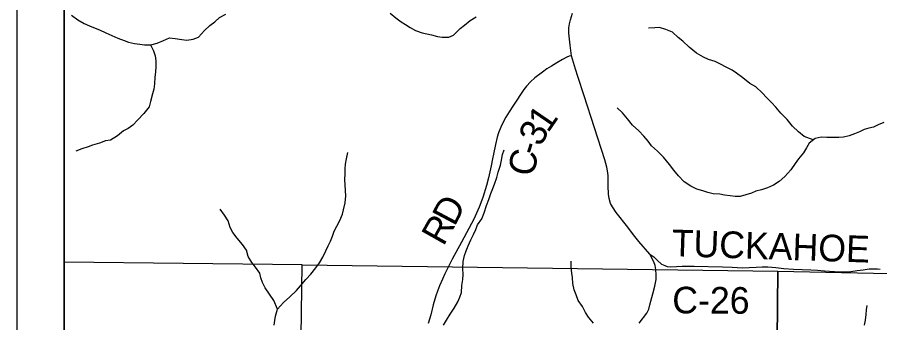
# Model space of a CAD drawing. Extents: x 0 to 34, y 0 to 22.
# Drawn here: x 23.417 to 25.254, y 19.532 to 20.183 of the extents above; entities that cross this region are included whole.
import ezdxf

# ---------------------------------------------------------------- set-up
doc = ezdxf.new("R2010")
doc.units = 0
for name, color, linetype in [('GM_X_Corporation', 7, 'Continuous'), ('GM_X_County_Road', 7, 'Continuous'), ('GM_X_County_Road_Text', 7, 'Continuous'), ('GM_X_Minor_River', 7, 'Continuous'), ('GM_X_State_Route', 7, 'Continuous'), ('SH_Data', 7, 'Continuous')]:
    doc.layers.add(name, color=color, linetype=linetype)

msp = doc.modelspace()

# ---------------------------------------------------------------- linework, layer by layer
at = {"layer": 'GM_X_Corporation'}
msp.add_lwpolyline([(27.0234, 16.6611), (27.0349, 17.5522), (27.0419, 17.8236), (27.0487, 18.5805), (27.0719, 19.3912), (27.0733, 19.498), (27.0761, 19.6806), (27.0864, 20.0138), (27.0885, 20.1139), (27.0907, 20.123), (27.0873, 20.2665), (27.0031, 20.2673), (26.7822, 20.2704), (26.7196, 20.2707), (26.6351, 20.2734), (26.5702, 20.276), (26.2533, 20.2773), (25.4507, 20.2949), (24.5249, 20.3107), (24.0688, 20.3165), (24.0328, 20.3169), (23.5167, 20.3276), (23.5167, 14.5642)], dxfattribs=at)
msp.add_lwpolyline([(27.0234, 16.6611), (27.0349, 17.5522), (27.0419, 17.8236), (27.0487, 18.5805), (27.0719, 19.3912), (27.0733, 19.498), (27.0761, 19.6806), (27.0864, 20.0138), (27.0885, 20.1139), (27.0907, 20.123), (27.0873, 20.2665), (27.0031, 20.2673), (26.7822, 20.2704), (26.7196, 20.2707), (26.6351, 20.2734), (26.5702, 20.276), (26.2533, 20.2773), (25.4507, 20.2949), (24.5249, 20.3107), (24.0688, 20.3165), (24.0328, 20.3169), (23.5167, 20.3276), (23.5167, 14.5642)], dxfattribs=at)
for points in [[(23.5167, 19.661), (23.5167, 18.6437), (24.0091, 18.6407), (24.0234, 19.6557)], [(24.0234, 19.6557), (25.037, 19.6422), (25.0268, 18.6245), (24.0091, 18.6407)], [(25.037, 19.6422), (26.0559, 19.6207), (26.0385, 18.6067), (25.0268, 18.6245)]]:
    msp.add_lwpolyline(points, close=True, dxfattribs=at)
at = {"layer": 'GM_X_County_Road'}
for points in [[(24.5973, 20.1011), (24.592, 20.1001), (24.5871, 20.0979), (24.5783, 20.093), (24.5663, 20.0861), (24.5546, 20.0791), (24.5448, 20.073), (24.5358, 20.0665), (24.519, 20.0542), (24.5099, 20.0458), (24.5013, 20.0361), (24.4956, 20.0291), (24.474, 19.996), (24.4644, 19.9818), (24.4573, 19.9703), (24.4516, 19.9598), (24.4466, 19.9489), (24.4421, 19.937), (24.4393, 19.9279), (24.4352, 19.912), (24.4312, 19.8916), (24.4293, 19.8817), (24.4262, 19.8665), (24.4203, 19.8412), (24.4163, 19.8248), (24.4086, 19.7989), (24.4007, 19.7785), (24.3896, 19.7527), (24.3632, 19.704), (24.3429, 19.6678), (24.3273, 19.6364), (24.3222, 19.6248), (24.3161, 19.6112), (24.3117, 19.5997), (24.3084, 19.5899), (24.3028, 19.5706), (24.2974, 19.549), (24.2923, 19.5303)], [(24.7643, 19.6782), (24.7726, 19.6728), (24.7804, 19.6649), (24.7889, 19.6569), (24.7959, 19.654), (24.8012, 19.6521), (24.8079, 19.6512), (24.8208, 19.6524), (24.8331, 19.653), (24.8583, 19.6529), (24.9193, 19.6513), (24.9395, 19.6508), (24.9607, 19.6494), (24.9906, 19.6507), (25.0035, 19.6514), (25.0158, 19.6513), (25.0329, 19.6499), (25.0497, 19.6477), (25.07, 19.6464), (25.0887, 19.6458), (25.1068, 19.645), (25.1211, 19.6441), (25.1362, 19.6432), (25.1573, 19.6411), (25.1669, 19.6405), (25.1783, 19.6404), (25.192, 19.6417), (25.2059, 19.6433), (25.2188, 19.6452), (25.2314, 19.6468), (25.2411, 19.6474), (25.2494, 19.6471), (25.2548, 19.6464)]]:
    msp.add_lwpolyline(points, dxfattribs=at)
at = {"layer": 'GM_X_Minor_River'}
for points in [[(24.2114, 20.1917), (24.2232, 20.1823), (24.2342, 20.1732), (24.2437, 20.1679), (24.254, 20.1615), (24.265, 20.1547), (24.2791, 20.1498), (24.2889, 20.1479), (24.2988, 20.1457), (24.3121, 20.1423), (24.3216, 20.1405), (24.336, 20.1409), (24.3459, 20.1451), (24.3599, 20.1592), (24.3693, 20.1664), (24.3818, 20.176), (24.3943, 20.1844)], [(23.5322, 20.1878), (23.5455, 20.1776), (23.5592, 20.1701), (23.5706, 20.1652), (23.5824, 20.1599), (23.5919, 20.1562), (23.6052, 20.1497), (23.6185, 20.1441), (23.6306, 20.1384), (23.6443, 20.1335), (23.6538, 20.1305), (23.6663, 20.1275), (23.6781, 20.1257), (23.688, 20.1242), (23.7009, 20.1242), (23.7149, 20.1281), (23.7282, 20.1338), (23.741, 20.1392), (23.7528, 20.1381), (23.7672, 20.1355), (23.7782, 20.1344), (23.7915, 20.1367), (23.8029, 20.1406), (23.8154, 20.155), (23.8271, 20.1657), (23.8373, 20.1737), (23.8472, 20.1825), (23.8612, 20.1901)], [(25.1122, 19.9218), (25.0931, 19.9292), (25.0806, 19.939), (25.068, 19.9515), (25.057, 19.9651), (25.0433, 19.9788), (25.0323, 19.9917), (25.0231, 20.0019), (25.0136, 20.0117), (25.0037, 20.022), (24.9897, 20.0348), (24.9771, 20.0424), (24.9623, 20.0545), (24.949, 20.0643), (24.9395, 20.0707), (24.927, 20.0768), (24.9148, 20.0832), (24.903, 20.0889), (24.8893, 20.093), (24.8787, 20.0979), (24.8639, 20.107), (24.8479, 20.1198), (24.8342, 20.1323), (24.8247, 20.1403), (24.8126, 20.1516), (24.7985, 20.1573), (24.7848, 20.1614), (24.7746, 20.1606), (24.7613, 20.1598)], [(23.7005, 20.1242), (23.7066, 20.1114), (23.7104, 20.1007), (23.7116, 20.0905), (23.7116, 20.0783), (23.7109, 20.0665), (23.7098, 20.0555), (23.709, 20.0415), (23.7079, 20.0297), (23.7049, 20.0198), (23.7008, 20.0038), (23.6974, 19.992), (23.686, 19.9783), (23.6732, 19.9646), (23.6626, 19.9532), (23.6531, 19.9459), (23.6429, 19.941), (23.6304, 19.9307), (23.6152, 19.9215), (23.605, 19.9196), (23.5917, 19.9149), (23.5773, 19.9107), (23.5674, 19.9073), (23.5542, 19.9027), (23.5413, 19.8981)], [(25.2623, 19.959), (25.2509, 19.954), (25.2407, 19.9487), (25.2308, 19.9471), (25.2206, 19.944), (25.2107, 19.9391), (25.2001, 19.9348), (25.1891, 19.9303), (25.1766, 19.9276), (25.1671, 19.9271), (25.1542, 19.9271), (25.141, 19.9267), (25.1288, 19.9274), (25.1163, 19.9251), (25.1038, 19.9152), (25.0977, 19.9053), (25.0913, 19.8946), (25.0811, 19.8813), (25.0739, 19.8717), (25.0645, 19.858), (25.0516, 19.8436), (25.0399, 19.8333), (25.0274, 19.8256), (25.0145, 19.8195), (25.0024, 19.8157), (24.9902, 19.8126), (24.9807, 19.8084), (24.969, 19.8045), (24.9569, 19.8011), (24.9462, 19.801), (24.9356, 19.8029), (24.9231, 19.8044), (24.9136, 19.8059), (24.8992, 19.8073), (24.8874, 19.8096), (24.8768, 19.8137), (24.8642, 19.8167), (24.8517, 19.8231), (24.8373, 19.8322), (24.8255, 19.8455), (24.8152, 19.8572), (24.806, 19.8693), (24.7931, 19.8852), (24.7802, 19.8977), (24.768, 19.9095), (24.7608, 19.9193), (24.7516, 19.9296), (24.741, 19.9409), (24.7273, 19.953), (24.7166, 19.9671), (24.706, 19.9799), (24.6946, 19.9902)], [(24.3887, 19.7205), (24.3936, 19.7312), (24.3973, 19.7407), (24.406, 19.7536), (24.4113, 19.7662), (24.4166, 19.7818), (24.4215, 19.7951), (24.4256, 19.808), (24.4294, 19.8183), (24.4332, 19.8278), (24.4384, 19.8419), (24.4414, 19.8529), (24.446, 19.8681), (24.4482, 19.8784), (24.4505, 19.8909), (24.4538, 19.9004)], [(23.9638, 19.5268), (23.9653, 19.5367), (23.9668, 19.5462), (23.9713, 19.5614), (23.9838, 19.5751), (23.9974, 19.5873), (24.0114, 19.6011), (24.0197, 19.6106), (24.0315, 19.6243), (24.0421, 19.6357), (24.0526, 19.6495), (24.0606, 19.6601), (24.0674, 19.6719), (24.0738, 19.6852), (24.0791, 19.6959), (24.084, 19.7062), (24.0881, 19.7164), (24.0915, 19.7275), (24.0972, 19.7381), (24.1036, 19.7503), (24.1093, 19.7633), (24.1119, 19.7728), (24.1153, 19.788), (24.1164, 19.8024), (24.116, 19.8134), (24.1152, 19.8267), (24.1148, 19.8362), (24.1151, 19.851), (24.1155, 19.8605), (24.1162, 19.8704), (24.1177, 19.8818), (24.1207, 19.8951)], [(23.9711, 19.5609), (23.9633, 19.58), (23.9538, 19.5929), (23.9446, 19.6069), (23.9393, 19.6183), (23.9358, 19.6282), (23.9331, 19.638), (23.924, 19.6505), (23.9164, 19.6604), (23.9088, 19.6733), (23.9053, 19.6866), (23.8966, 19.6987), (23.8848, 19.7127), (23.8756, 19.7248), (23.8703, 19.7355), (23.8657, 19.7495), (23.8581, 19.7616), (23.8486, 19.7745)], [(24.3243, 19.5273), (24.3307, 19.5379), (24.3386, 19.5505), (24.3473, 19.5634), (24.3549, 19.5768), (24.3598, 19.5867), (24.3628, 19.5966), (24.3639, 19.6114), (24.3661, 19.6247), (24.3665, 19.6353), (24.3657, 19.6482), (24.3664, 19.6627), (24.3694, 19.6752), (24.3728, 19.6855), (24.3773, 19.6962), (24.3826, 19.7091), (24.3887, 19.7205)], [(24.6441, 19.531), (24.6335, 19.5443), (24.6274, 19.5541), (24.6205, 19.567), (24.6117, 19.5795), (24.6072, 19.5917), (24.6033, 19.6023), (24.6003, 19.6156), (24.5991, 19.6285), (24.5983, 19.638), (24.5964, 19.6517), (24.5964, 19.6638)], [(25.2213, 19.5272), (25.2235, 19.5378), (25.225, 19.55), (25.2254, 19.5595), (25.2269, 19.569)]]:
    msp.add_lwpolyline(points, dxfattribs=at)
at = {"layer": 'GM_X_State_Route'}
msp.add_lwpolyline([(24.7417, 19.5316), (24.7577, 19.5526), (24.7617, 19.561), (24.7644, 19.5702), (24.7708, 19.5936), (24.7749, 19.6103), (24.7776, 19.6243), (24.7776, 19.6346), (24.7767, 19.6455), (24.7754, 19.6541), (24.7724, 19.6624), (24.7643, 19.6782), (24.7411, 19.7052), (24.7292, 19.7199), (24.7173, 19.7356), (24.6926, 19.7675), (24.6848, 19.7792), (24.6805, 19.7867), (24.6772, 19.7969), (24.676, 19.8065), (24.6757, 19.8239), (24.6752, 19.8459), (24.6743, 19.8558), (24.6728, 19.8638), (24.6684, 19.8793), (24.6461, 19.9475), (24.6246, 20.0156), (24.6109, 20.0569), (24.6057, 20.0723), (24.5973, 20.1011), (24.5943, 20.124), (24.5915, 20.1494), (24.5914, 20.1607), (24.5931, 20.1695), (24.5953, 20.1775), (24.5993, 20.1917)], dxfattribs=at)
at = {"layer": 'SH_Data'}
for points in [[(23.4167, 21), (30.4167, 21), (30.4167, 14), (23.4167, 14)], [(23.5167, 20.9), (30.3167, 20.9), (30.3167, 14.1), (23.5167, 14.1)]]:
    msp.add_lwpolyline(points, close=True, dxfattribs=at)

# ---------------------------------------------------------------- texts
at = {"layer": 'GM_X_County_Road_Text'}
for s, height, rotation, p in [('1', 0.0568, 55.6662, (24.5472, 19.9351)), ('3', 0.0568, 61.9826, (24.5316, 19.9056)), ('C', 0.0568, 77.8924, (24.5163, 19.8416)), ('-', 0.0568, 72.5426, (24.5257, 19.8859)), ('D', 0.0568, 62.048, (24.3481, 19.7357)), ('R', 0.0568, 60.6516, (24.3245, 19.6937)), ('TUCKAHOE', 0.05682, 358.1241, (24.81, 19.6742)), ('C-26', 0.05682, 359.6571, (24.8118, 19.5523))]:
    msp.add_text(s, height=height, rotation=rotation, dxfattribs=at).set_placement(p)

doc.saveas('drawing.dxf')
